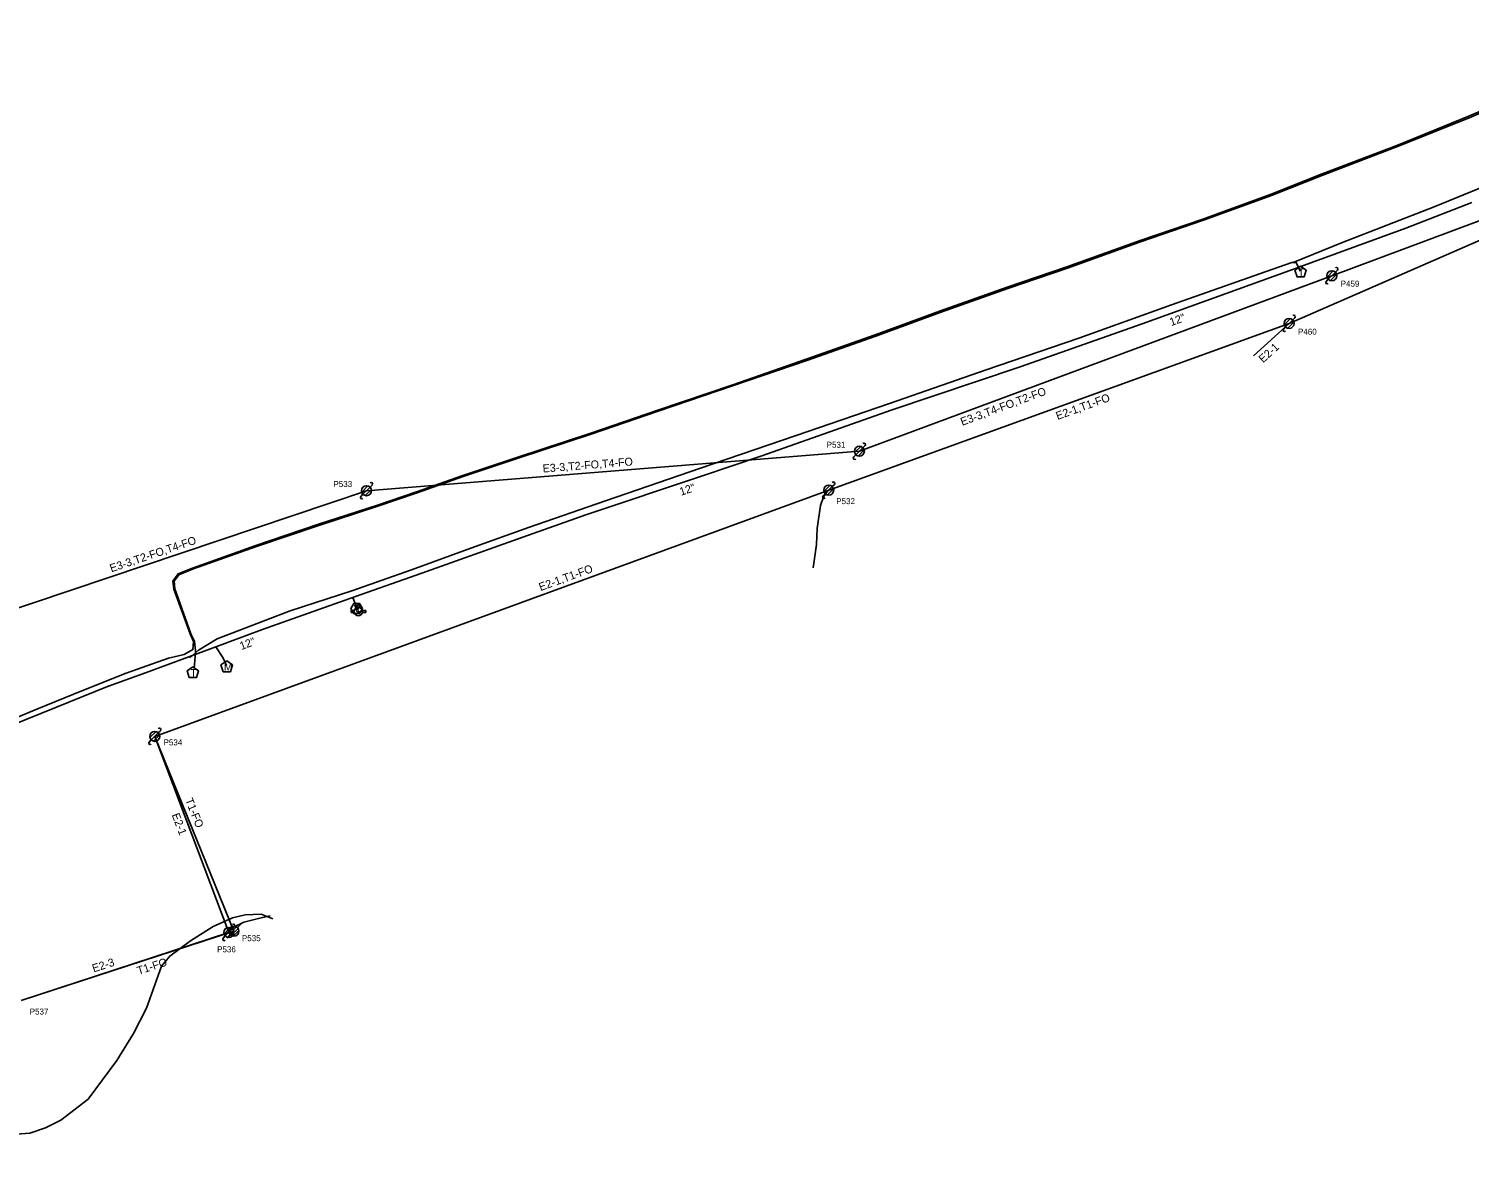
# Model space of a CAD drawing. Extents: x 1614474 to 1865144, y 1098877 to 1212550.
# Drawn here: x 1813627 to 1814347, y 1189785 to 1190349 of the extents above; entities that cross this region are included whole.
import ezdxf

# ---------------------------------------------------------------- set-up
doc = ezdxf.new("R2010")
doc.units = 0
for name, color, linetype in [('RD_EX_SU_Elec', 7, 'Continuous'), ('RD_EX_SU_H2O', 7, 'Continuous'), ('RD_EX_SU_Ovhd', 7, 'Continuous'), ('RD_EX_SU_Pole', 7, 'Continuous'), ('RD_EX_SU_Telecom', 7, 'Continuous'), ('RD_EX_SU_TX_H2O', 7, 'Continuous'), ('RD_EX_SU_TX_Pole', 7, 'Continuous')]:
    doc.layers.add(name, color=color, linetype=linetype)

# ---------------------------------------------------------------- blocks, each defined once
blk = doc.blocks.new('SUE_TPP')
at = {"layer": 'RD_EX_SU_Telecom'}
blk.add_lwpolyline([(0, 3), (-2.85, 0.93), (-1.76, -2.43), (1.76, -2.43), (2.85, 0.93)], close=True, dxfattribs=at)
blk.add_text('T', height=3.75, dxfattribs=at).set_placement((-1.25, -1.88))
blk = doc.blocks.new('SUE_PP')
at = {"layer": 'RD_EX_SU_Pole'}
for p, q in [((-2.41, -0.65), (0.65, 2.41)), ((-1.77, -1.77), (1.77, 1.77)), ((-0.65, -2.41), (2.41, 0.65)), ((1.77, 1.77), (2.83, 2.83)), ((-2.83, -2.83), (-1.77, -1.77))]:
    blk.add_line(p, q, dxfattribs=at)
blk.add_circle((0, 0), 2.5, dxfattribs=at)
for centre, start, end in [((2.3, 3.36), 315, 135), ((-2.3, -3.36), 135, 315)]:
    blk.add_arc(centre, 0.75, start, end, dxfattribs=at)
blk = doc.blocks.new('SUE_PTP')
at = {"layer": 'RD_EX_SU_Pole'}
for p, q in [((-2.48, -0.33), (0.33, 2.48)), ((-2.1, -1.36), (1.36, 2.1)), ((-1.4, -2.08), (2.08, 1.4)), ((-0.38, -2.47), (2.47, 0.38)), ((1.77, 1.77), (3.42, 3.42)), ((-3.42, -3.42), (-1.77, -1.77)), ((1.52, -1.99), (1.99, -1.52))]:
    blk.add_line(p, q, dxfattribs=at)
blk.add_circle((0, 0), 2.5, dxfattribs=at)
blk = doc.blocks.new('SUE_WV')
at = {"layer": 'RD_EX_SU_H2O'}
blk.add_lwpolyline([(2.89, 0), (1.44, 2.5), (-1.44, 2.5), (-2.89, 0), (-1.44, -2.5), (1.44, -2.5)], close=True, dxfattribs=at)
blk.add_text('V', height=3.75, dxfattribs=at).set_placement((-1.43, -1.88))
blk = doc.blocks.new('SUE_WFH')
at = {"layer": 'RD_EX_SU_H2O'}
for p, q in [((-2.01, 0.6), (-3.65, 0.6)), ((-3.65, 0.6), (-3.65, -0.45)), ((-0.48, 3.38), (-0.48, 2.04)), ((0.57, 3.38), (-0.48, 3.38)), ((0.57, 2.02), (0.57, 3.38)), ((3.7, 0.6), (2.01, 0.6)), ((3.7, -0.45), (3.7, 0.6)), ((-3.65, -0.45), (-2.05, -0.45)), ((2.05, -0.45), (3.7, -0.45))]:
    blk.add_line(p, q, dxfattribs=at)
for radius in [2.1, 0.263]:
    blk.add_circle((0, 0), radius, dxfattribs=at)
for start, end in [(163.3387, 192.31502), (74.24552, 103.21276), (347.68498, 16.6613)]:
    blk.add_arc((0, 0), 2.1, start, end, dxfattribs=at)
blk = doc.blocks.new('SUE_WM')
at = {"layer": 'RD_EX_SU_H2O'}
blk.add_lwpolyline([(0, 3.05), (-2.9, 0.94), (-1.79, -2.47), (1.79, -2.47), (2.9, 0.94)], close=True, dxfattribs=at)
blk.add_text('M', height=3.75, dxfattribs=at).set_placement((-1.43, -1.88))

msp = doc.modelspace()

# ---------------------------------------------------------------- linework, layer by layer
at = {"layer": 'RD_EX_SU_Elec'}
for points in [[(1814019.01, 1190079.23), (1814020.61, 1190090.85), (1814021.03, 1190098.94), (1814022.67, 1190110.31), (1814024.22, 1190114.73), (1814026.16, 1190117.58)], [(1813726.79, 1189896.86), (1813728.95, 1189899.42), (1813734.41, 1189902.16), (1813743.83, 1189904.43), (1813747.6, 1189905.23)]]:
    msp.add_lwpolyline(points, dxfattribs=at)
at = {"layer": 'RD_EX_SU_H2O'}
msp.add_line((1813788.94, 1190064.41), (1813791.32, 1190058.18), dxfattribs=at)
for points in [[(1813666.9, 1190020.07), (1813685.36, 1190026.82), (1813719.15, 1190039.28), (1813743.35, 1190048.26), (1813790.21, 1190064.84), (1813823.35, 1190076.52), (1813873.92, 1190094.55), (1813905.45, 1190105.71), (1813963.7, 1190125.13), (1813993.4, 1190135.25), (1814058.04, 1190158.07), (1814122.55, 1190179.66), (1814183.45, 1190201.14), (1814255.4, 1190227.12), (1814315.19, 1190248.98), (1814348.18, 1190261.86)], [(1813720.47, 1190039.76), (1813723.98, 1190034.49), (1813725.78, 1190030.36)], [(1813049.93, 1189785.18), (1813062.98, 1189793.04), (1813077.41, 1189801.91), (1813100.8, 1189813.52), (1813124.24, 1189823.21), (1813173.48, 1189839.48), (1813207.95, 1189850.5), (1813242.12, 1189860.74), (1813307.93, 1189883.34), (1813347.93, 1189899.33), (1813402.79, 1189918.54), (1813471.7, 1189944.89), (1813528.83, 1189966.2), (1813605.69, 1189995.43), (1813667.12, 1190020.2)]]:
    msp.add_lwpolyline(points, dxfattribs=at)
at = {"layer": 'RD_EX_SU_Ovhd'}
for p, q in [((1814256.92, 1190201.37), (1814512.77, 1190312.92)), ((1814278.27, 1190225.21), (1814512.77, 1190312.92)), ((1814042.12, 1190137.49), (1814278.27, 1190225.21)), ((1814026.8, 1190118.06), (1814256.92, 1190201.37)), ((1814239.04, 1190185.1), (1814256.92, 1190201.37)), ((1813795.78, 1190117.77), (1814042.12, 1190137.49)), ((1813557.25, 1190037.52), (1813795.78, 1190117.77)), ((1813689.95, 1189995), (1814026.8, 1190118.06)), ((1813689.95, 1189995), (1813726.98, 1189897)), ((1813689.95, 1189995), (1813729.49, 1189897.64)), ((1813623.17, 1189863), (1813729.49, 1189897.64)), ((1813623.17, 1189863), (1813726.98, 1189897))]:
    msp.add_line(p, q, dxfattribs=at)
at = {"layer": 'RD_EX_SU_Pole'}
for p, q in [((1814275.85, 1190224.56), (1814278.91, 1190227.62)), ((1814276.5, 1190223.44), (1814280.03, 1190226.97)), ((1814277.62, 1190222.79), (1814280.68, 1190225.85)), ((1814280.03, 1190226.97), (1814281.1, 1190228.03)), ((1814275.44, 1190222.38), (1814276.5, 1190223.44)), ((1814254.51, 1190200.73), (1814257.57, 1190203.79)), ((1814255.15, 1190199.6), (1814258.69, 1190203.14)), ((1814258.69, 1190203.14), (1814259.75, 1190204.2)), ((1814254.09, 1190198.54), (1814255.15, 1190199.6)), ((1814256.27, 1190198.96), (1814259.33, 1190202.02)), ((1814039.7, 1190136.84), (1814042.77, 1190139.9)), ((1814040.35, 1190135.72), (1814043.89, 1190139.25)), ((1814041.47, 1190135.07), (1814044.53, 1190138.13)), ((1814043.89, 1190139.25), (1814044.95, 1190140.32)), ((1814039.29, 1190134.66), (1814040.35, 1190135.72)), ((1813792.95, 1190114.94), (1813794.01, 1190116)), ((1813793.37, 1190117.12), (1813796.43, 1190120.19)), ((1813794.01, 1190116), (1813797.55, 1190119.54)), ((1813795.13, 1190115.36), (1813798.19, 1190118.42)), ((1813797.55, 1190119.54), (1813798.61, 1190120.6)), ((1814023.97, 1190115.23), (1814025.03, 1190116.29)), ((1814024.38, 1190117.41), (1814027.45, 1190120.47)), ((1814025.03, 1190116.29), (1814028.57, 1190119.83)), ((1814026.15, 1190115.64), (1814029.21, 1190118.71)), ((1814028.57, 1190119.83), (1814029.63, 1190120.89))]:
    msp.add_line(p, q, dxfattribs=at)
for centre in [(1814278.27, 1190225.21), (1814256.92, 1190201.37), (1814042.12, 1190137.49), (1813795.78, 1190117.77), (1814026.8, 1190118.06)]:
    msp.add_circle(centre, 2.5, dxfattribs=at)
for centre, start, end in [((1814280.56, 1190228.56), 315, 135), ((1814275.97, 1190221.85), 135, 315), ((1814259.22, 1190204.73), 315, 135), ((1814254.62, 1190198.01), 135, 315), ((1814044.42, 1190140.85), 315, 135), ((1814039.82, 1190134.13), 135, 315), ((1813798.08, 1190121.13), 315, 135), ((1814029.1, 1190121.42), 315, 135), ((1813793.48, 1190114.41), 135, 315), ((1814024.5, 1190114.7), 135, 315)]:
    msp.add_arc(centre, 0.75, start, end, dxfattribs=at)
at = {"layer": 'RD_EX_SU_Telecom'}
for points in [[(1814258.86, 1190231.84), (1814283.17, 1190241.59), (1814329.35, 1190259.72), (1814377.11, 1190279.06), (1814410.53, 1190292.69), (1814442.38, 1190306.97), (1814491.28, 1190328.65), (1814536.38, 1190350.25), (1814582.23, 1190372.28), (1814630.58, 1190396.72), (1814674, 1190419.8), (1814715.76, 1190442.48), (1814758.2, 1190465.88), (1814801.42, 1190489.78), (1814843.45, 1190513.06), (1814886.77, 1190537.18), (1814928.38, 1190560.47), (1814957.21, 1190576.47), (1814984.74, 1190592.92), (1815004.59, 1190603.88), (1815010.03, 1190605.79), (1815012.02, 1190604.38), (1815016.84, 1190596.93), (1815019.44, 1190591.97)], [(1813605.76, 1189998.02), (1813630.95, 1190008.57), (1813653.44, 1190017.8), (1813675.6, 1190026.6), (1813696.88, 1190034), (1813704.65, 1190035.96), (1813708.99, 1190038.4), (1813709.34, 1190042.34), (1813707.69, 1190046.24), (1813699.51, 1190068.56), (1813699, 1190072.59), (1813701.64, 1190076.22), (1813708.75, 1190078.98), (1813740.53, 1190090.42), (1813771.36, 1190100.84), (1813801.34, 1190110.54), (1813820.83, 1190117.24), (1813843.89, 1190125.35), (1813871.42, 1190134.58), (1813907.91, 1190146.47), (1813941.36, 1190158.08), (1813978.87, 1190170.76), (1814015.55, 1190183.46), (1814050.04, 1190195.67), (1814082.22, 1190207.54), (1814116.04, 1190219.47), (1814145.85, 1190229.72), (1814182.41, 1190242.9), (1814213.81, 1190253.56), (1814247.99, 1190266.01), (1814273.44, 1190276.11), (1814310.82, 1190290.35), (1814346.19, 1190304.73), (1814380.05, 1190319.02)], [(1813709.6, 1190028.99), (1813710.16, 1190034.86), (1813710.38, 1190037.96), (1813709.87, 1190042.49), (1813708.01, 1190046.22), (1813699.98, 1190068.7), (1813699.57, 1190072.57), (1813702.04, 1190075.68), (1813708.79, 1190078.53), (1813740.84, 1190089.88), (1813771.46, 1190100.23), (1813801.49, 1190109.99), (1813821.04, 1190116.72), (1813844.07, 1190124.8), (1813871.59, 1190134.03), (1813908.02, 1190145.99), (1813941.57, 1190157.6), (1813979.17, 1190170.32), (1814015.89, 1190182.88), (1814050.31, 1190195.09), (1814082.44, 1190206.85), (1814116.27, 1190218.86), (1814146.09, 1190228.93), (1814182.67, 1190242.2), (1814214.06, 1190253.01), (1814248.14, 1190265.38), (1814273.74, 1190275.47), (1814311.03, 1190289.76), (1814346.59, 1190304.01), (1814380.34, 1190318.45)], [(1813707.49, 1190034.2), (1813711.74, 1190038.08), (1813721.12, 1190043.75), (1813757.58, 1190057.77), (1813788.37, 1190067.76), (1813818.25, 1190078.26), (1813847.89, 1190089.1), (1813876.72, 1190099.35), (1813915.17, 1190112.76), (1813962.66, 1190129.1), (1814010.08, 1190145.21), (1814057.1, 1190161.36), (1814105.53, 1190178.16), (1814151.79, 1190193.97), (1814198.07, 1190210.72), (1814245.39, 1190227.39), (1814258.24, 1190231.78), (1814260.49, 1190231.85), (1814262.5, 1190227.5)], [(1813602.71, 1189794.8), (1813627.54, 1189796.74), (1813635.4, 1189799.31), (1813643, 1189803.23), (1813656.7, 1189813.75), (1813670.93, 1189832.96), (1813679.35, 1189846.45), (1813685.82, 1189859.2), (1813693.37, 1189880.09), (1813697.42, 1189885.15), (1813707.84, 1189892.75), (1813719.15, 1189899.96), (1813728.8, 1189904.32), (1813735.17, 1189905.78), (1813743.14, 1189906.07), (1813749, 1189903.88)]]:
    msp.add_lwpolyline(points, dxfattribs=at)

# ---------------------------------------------------------------- block references
at = {"layer": 'RD_EX_SU_H2O'}
for name, p in [('SUE_WV', (1813790.84, 1190058.83)), ('SUE_WFH', (1813791.7, 1190057.35)), ('SUE_WM', (1813725.94, 1190029.73))]:
    msp.add_blockref(name, p, dxfattribs=at)
at = {"layer": 'RD_EX_SU_Pole'}
for p in [(1813689.95, 1189995), (1813726.98, 1189897)]:
    msp.add_blockref('SUE_PP', p, dxfattribs=at)
at = {"layer": 'RD_EX_SU_Telecom'}
for name, p in [('SUE_TPP', (1814262.64, 1190227.03)), ('SUE_TPP', (1813708.98, 1190026.78)), ('SUE_PTP', (1813729.49, 1189897.64))]:
    msp.add_blockref(name, p, dxfattribs=at)

# ---------------------------------------------------------------- texts
at = {"layer": 'RD_EX_SU_Ovhd'}
for s, rotation, p in [('E2-1', 42.30235, (1814243.9, 1190181.42)), ('E3-3,T4-FO,T2-FO', 20.37802, (1814093.52, 1190150.18)), ('E2-1,T1-FO', 19.90221, (1814141.2, 1190153.1)), ('E3-3,T2-FO,T4-FO', 4.57593, (1813884, 1190126.84)), ('E3-3,T2-FO,T4-FO', 18.59547, (1813668.23, 1190076.97)), ('E2-1,T1-FO', 20.06863, (1813882.78, 1190067.58)), ('T1-FO', 292.1026, (1813705.03, 1189963.19)), ('E2-1', 290.69651, (1813698.36, 1189955.77)), ('E2-3', 18.13107, (1813659.42, 1189876.98)), ('T1-FO', 18.0446, (1813681.84, 1189875.81))]:
    msp.add_text(s, height=4, rotation=rotation, dxfattribs=at).set_placement(p)
at = {"layer": 'RD_EX_SU_TX_H2O'}
for rotation, p in [(19.8514, (1814198, 1190200.02)), (18.43076, (1813953.01, 1190115.24)), (20.35832, (1813733.24, 1190038.11))]:
    msp.add_text('12"', height=4, rotation=rotation, dxfattribs=at).set_placement(p)
at = {"layer": 'RD_EX_SU_TX_Pole'}
for s, p in [('P459', (1814282.68, 1190219.74)), ('P460', (1814261.35, 1190195.73)), ('P531', (1814025.76, 1190139.23)), ('P533', (1813779.24, 1190119.6)), ('P532', (1814030.54, 1190111.06)), ('P534', (1813694.34, 1189990.48)), ('P535', (1813733.5, 1189892.64)), ('P536', (1813721.1, 1189887.07)), ('P537', (1813627.43, 1189855.96))]:
    msp.add_text(s, height=3, dxfattribs=at).set_placement(p)

doc.saveas('drawing.dxf')
